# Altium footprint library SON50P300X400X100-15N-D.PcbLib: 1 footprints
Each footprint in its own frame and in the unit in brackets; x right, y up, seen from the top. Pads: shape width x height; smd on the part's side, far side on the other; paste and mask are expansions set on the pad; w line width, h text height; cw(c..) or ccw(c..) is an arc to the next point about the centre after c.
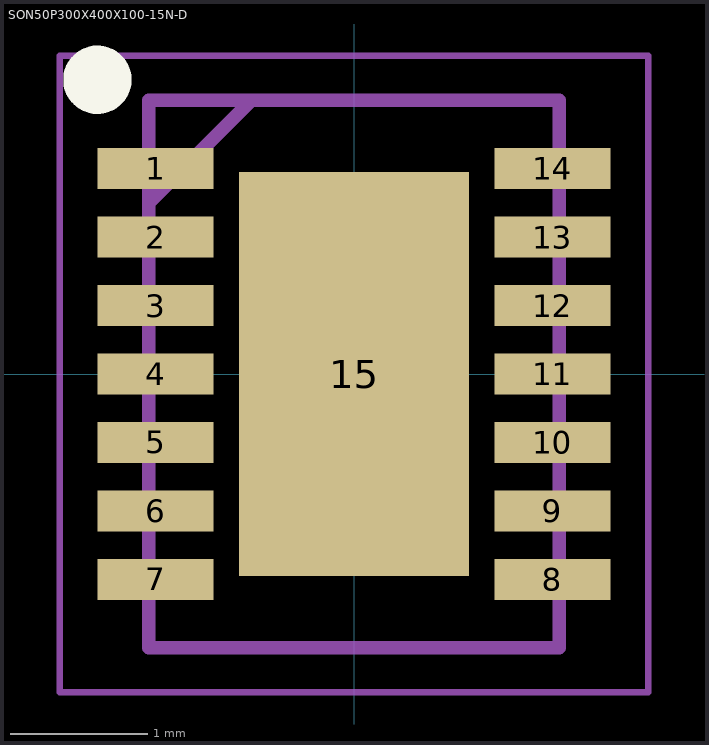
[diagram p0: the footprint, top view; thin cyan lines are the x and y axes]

## SON50P300X400X100-15N-D [mm]
pads (15):
  rect 0.85x0.3 smd: 1(-1.45,1.5) 2(-1.45,1) 3(-1.45,0.5) 4(-1.45,0) 5(-1.45,-0.5) 6(-1.45,-1) 7(-1.45,-1.5) 8(1.45,-1.5) 9(1.45,-1) 10(1.45,-0.5) 11(1.45,0) 12(1.45,0.5) 13(1.45,1) 14(1.45,1.5)
  rect 1.68x2.95 smd: 15(0,0)
Top Overlay:
  circle w0.25: c-1.875,2.15 r0.125
Mechanical 15:
  lines w0.1: -1.5,1.25 -0.75,2 ; -1.5,-2 1.5,-2 1.5,2 -1.5,2 -1.5,-2
Mechanical 20:
  lines w0.05: -2.15,-2.325 2.15,-2.325 2.15,2.325 -2.15,2.325 -2.15,-2.325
